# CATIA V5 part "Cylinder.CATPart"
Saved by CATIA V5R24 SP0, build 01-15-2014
Part number: Cylinder
Bounding box of the stored display mesh (mm): x -50 to 50, y -30 to 30, z -30 to 30
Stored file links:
  C:\Users\minsi\Google 드라이브\CDL_2019\00_CLASS\00_CAD\기말고사\DMU\Cylinder.CATPart
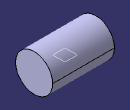
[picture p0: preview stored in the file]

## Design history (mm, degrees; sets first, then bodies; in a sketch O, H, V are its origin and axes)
Body1 (main body)
  Sketch1 on yz-plane, origin (0, 0, 0), H (0, 1, 0), V (0, 0, 1)
    circle A1 centre (0, 0) radius 30
    radius A1 = 30
  Pad1: profile Sketch1, direction (1, 0, 0), length 50, mirrored extent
